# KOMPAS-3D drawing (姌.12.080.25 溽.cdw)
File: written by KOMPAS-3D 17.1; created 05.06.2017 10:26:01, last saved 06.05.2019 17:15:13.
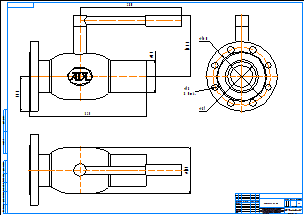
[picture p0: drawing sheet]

Sheet 1: A1, landscape

Title block, sheet 1: name: КШ.12.080.25 фс; material: Внимание! Данный продукт является объектом авторского права ООО «Торговый Дом АДЛ». / Запрещается изменение, копирование, распространение / (в том числе путем копирования на другие сайты и ресурсы в Интернете) / или любое иное использование информации и объектов без предварительного / согласия правообладателя (ООО «Торговый Дом АДЛ»).; sheets: 1; organisation: ООО "Торговый дом АДЛ"; sheet format: A1; stored path: C:\Users\kka\KOMPAS_Work\Модели кранов для исследований\Все краники\Редуцированный резьба-сварка ШК БИВАЛ\КШ.02.015.40 рс.cdw

Views: Вид 1, Проекционный вид 2, Проекционный вид 3
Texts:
  Klimkovich
  ADL
Dimensions and other numbers on the sheet: 168,8; 280; 89; 325; 160; 97,5; 81; 18; 8 Отв.; 127; 1:1; 1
